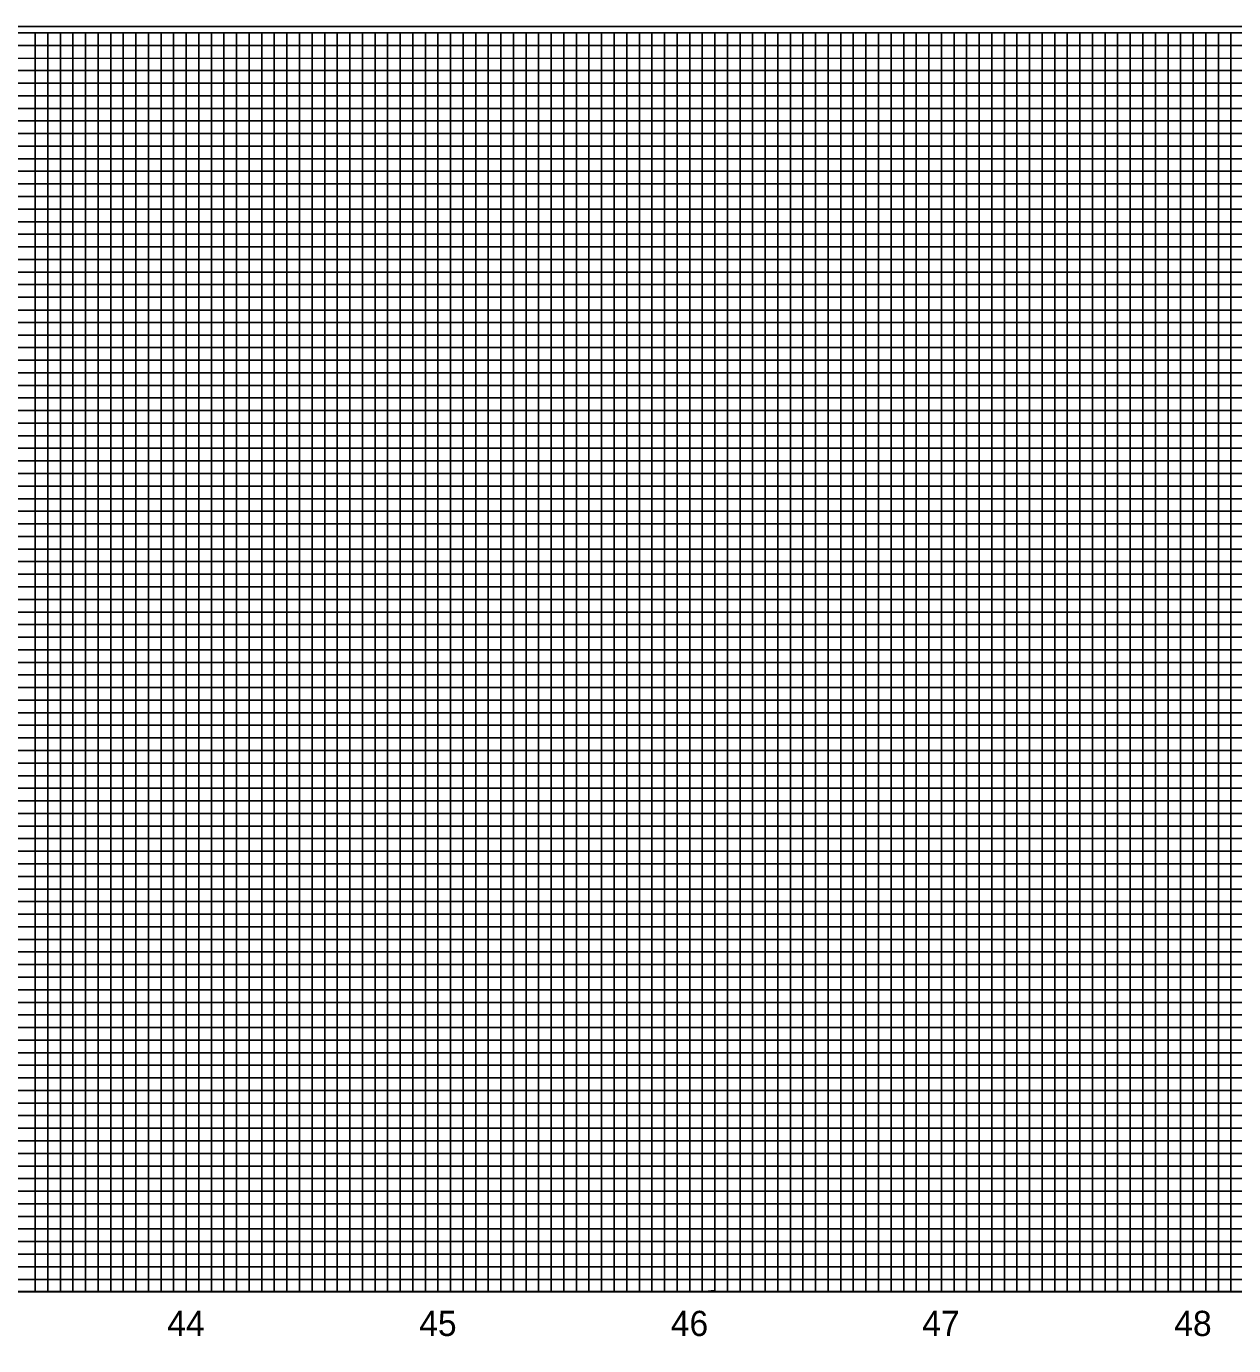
# Model space of a CAD drawing. Extents: x 1755181 to 1757273, y 729911 to 735411.
# Drawn here: x 1755934 to 1756414, y 733764 to 734288 of the extents above; entities that cross this region are included whole.
import ezdxf

# ---------------------------------------------------------------- set-up
doc = ezdxf.new("R2010")
doc.units = 0
for name, color, linetype in [('Exist Vertical Profile Horizontal Axis Label Major', 7, 'Continuous'), ('Scratch_Level_3', 7, 'Continuous'), ('Sheet DOT Grid CELL', 7, 'Continuous'), ('Sheet Plot Border Inside CELL', 7, 'Continuous'), ('Sheet Profile CELL', 7, 'Continuous'), ('Sheet Profile Grid Major CELL', 7, 'Continuous'), ('Sheet Profile Grid Middle CELL', 7, 'Continuous'), ('Sheet Profile Grid Minor CELL', 7, 'Continuous')]:
    doc.layers.add(name, color=color, linetype=linetype)

msp = doc.modelspace()

# ---------------------------------------------------------------- linework, layer by layer
at = {"layer": 'Scratch_Level_3'}
msp.add_lwpolyline([(1755397.67, 733785.92), (1755397.67, 734285.78), (1756647.65, 734285.78), (1756647.63, 734052.8), (1756797.72, 734052.78), (1756797.72, 733785.92)], close=True, dxfattribs=at)
at = {"layer": 'Sheet DOT Grid CELL'}
for p, q in [((1755947.67, 733785.78), (1755947.67, 734285.78)), ((1755997.67, 733785.78), (1755997.67, 734285.78)), ((1756047.67, 733785.78), (1756047.67, 734285.78)), ((1756097.67, 733785.78), (1756097.67, 734285.78)), ((1756147.67, 733785.78), (1756147.67, 734285.78)), ((1756197.67, 733785.78), (1756197.67, 734285.78)), ((1756247.67, 733785.78), (1756247.67, 734285.78)), ((1756297.67, 733785.78), (1756297.67, 734285.78)), ((1756347.67, 733785.78), (1756347.67, 734285.78)), ((1756397.67, 733785.78), (1756397.67, 734285.78)), ((1756647.62, 734235.78), (1755347.67, 734235.78)), ((1756647.62, 734185.78), (1755347.67, 734185.78)), ((1756647.67, 734135.78), (1755347.67, 734135.78)), ((1756647.63, 734085.78), (1755347.67, 734085.78)), ((1756847.67, 734035.78), (1755347.67, 734035.78)), ((1756847.67, 733985.78), (1755347.67, 733985.78)), ((1756847.67, 733935.78), (1755347.67, 733935.78)), ((1756847.67, 733885.78), (1755347.67, 733885.78)), ((1756847.67, 733835.78), (1755347.67, 733835.78))]:
    msp.add_line(p, q, dxfattribs=at)
at = {"layer": 'Sheet Plot Border Inside CELL'}
msp.add_lwpolyline([(1755193.67, 733233.23), (1756860.17, 733233.23), (1756860.17, 734288.33), (1755193.67, 734288.33)], close=True, dxfattribs=at)
at = {"layer": 'Sheet Profile CELL'}
msp.add_line((1755347.67, 733785.78), (1756847.67, 733785.78), dxfattribs=at)
msp.add_lwpolyline([(1756847.67, 734285.78), (1755347.67, 734285.78), (1755347.67, 733235.78), (1756847.67, 733235.78)], close=True, dxfattribs=at)
at = {"layer": 'Sheet Profile Grid Major CELL'}
for points in [[(1755897.67, 733785.78), (1755947.67, 733785.78), (1755947.67, 734285.78), (1755997.67, 734285.78), (1755997.67, 733785.78), (1756047.67, 733785.78), (1756047.67, 734285.78), (1756097.67, 734285.78), (1756097.67, 733785.78), (1756147.67, 733785.78), (1756147.67, 734285.78), (1756197.67, 734285.78), (1756197.67, 733785.78), (1756247.67, 733785.78), (1756247.67, 734285.78), (1756297.67, 734285.78), (1756297.67, 733785.78), (1756347.67, 733785.78), (1756347.67, 734285.78), (1756397.67, 734285.78), (1756397.67, 733785.78), (1756447.67, 733785.78)], [(1755347.67, 734235.78), (1756647.67, 734235.78)], [(1756647.67, 734185.78), (1755347.67, 734185.78), (1755347.67, 734135.78), (1756647.67, 734135.78)], [(1756647.63, 734085.78), (1755347.67, 734085.78), (1755347.67, 734035.78), (1756847.67, 734035.78)], [(1756847.67, 733985.78), (1755347.67, 733985.78), (1755347.67, 733935.78), (1756847.67, 733935.78)], [(1756847.67, 733885.78), (1755347.67, 733885.78), (1755347.67, 733885.78), (1755347.67, 733835.78), (1756847.67, 733835.78)]]:
    msp.add_lwpolyline(points, dxfattribs=at)
at = {"layer": 'Sheet Profile Grid Middle CELL'}
msp.add_line((1755347.67, 734260.78), (1756647.62, 734260.78), dxfattribs=at)
for points in [[(1755922.67, 733785.78), (1755972.67, 733785.78), (1755972.67, 733785.78), (1755972.67, 734285.78), (1756022.67, 734285.78), (1756022.67, 733785.78), (1756072.67, 733785.78), (1756072.67, 734285.78), (1756122.67, 734285.78), (1756122.67, 733785.78), (1756172.67, 733785.78), (1756172.67, 734285.78), (1756222.67, 734285.78), (1756222.67, 733785.78), (1756272.67, 733785.78), (1756272.67, 734285.78), (1756322.67, 734285.78), (1756322.67, 733785.78), (1756372.67, 733785.78), (1756372.67, 734285.78), (1756422.67, 734285.78)], [(1756647.67, 734210.78), (1755347.67, 734210.78), (1755347.67, 734160.78), (1756647.67, 734160.78)], [(1756647.62, 734110.78), (1755347.67, 734110.78), (1755347.67, 734060.78), (1756647.63, 734060.78)], [(1756847.67, 734010.78), (1755347.67, 734010.78), (1755347.67, 733960.78), (1756847.67, 733960.78)], [(1756847.67, 733910.78), (1755347.67, 733910.78), (1755347.67, 733860.78), (1756847.67, 733860.78)], [(1756847.67, 733810.78), (1755347.67, 733810.78)]]:
    msp.add_lwpolyline(points, dxfattribs=at)
at = {"layer": 'Sheet Profile Grid Minor CELL'}
for p, q in [((1755397.67, 734280.78), (1756647.67, 734280.78)), ((1756647.67, 734275.78), (1755397.67, 734275.43)), ((1755397.67, 734270.78), (1756647.67, 734270.78)), ((1756647.62, 734150.78), (1755397.67, 734150.78)), ((1756647.67, 734145.78), (1755397.67, 734145.78)), ((1756647.67, 734140.78), (1755397.67, 734140.78)), ((1755397.67, 734130.78), (1756647.67, 734130.78)), ((1756647.67, 734125.78), (1755397.67, 734125.78)), ((1755397.67, 734120.78), (1756647.62, 734120.78)), ((1756647.62, 734100.78), (1755397.67, 734100.78)), ((1755397.67, 734095.78), (1756647.62, 734095.78)), ((1756647.63, 734075.78), (1755397.67, 734075.78)), ((1755397.67, 734070.78), (1756647.63, 734070.78)), ((1756797.67, 734050.78), (1755397.67, 734050.78)), ((1755397.67, 734045.78), (1756797.67, 734045.78)), ((1756797.67, 734040.78), (1755397.67, 734040.78)), ((1755397.67, 734030.78), (1756797.67, 734030.78)), ((1756797.67, 734025.78), (1755397.67, 734025.78)), ((1755397.67, 734020.78), (1756797.67, 734020.78)), ((1756797.67, 734015.78), (1755397.67, 734015.78)), ((1755397.67, 734005.78), (1756797.67, 734005.78)), ((1756797.67, 734000.78), (1755397.67, 734000.78)), ((1755397.67, 733995.78), (1756797.67, 733995.78)), ((1756797.67, 733990.78), (1755397.67, 733990.78)), ((1755397.67, 733980.78), (1756797.67, 733980.78)), ((1756797.67, 733975.78), (1755397.67, 733975.78)), ((1755397.67, 733970.78), (1756797.67, 733970.78)), ((1756797.67, 733965.78), (1755397.67, 733965.78)), ((1755397.67, 733955.78), (1756797.67, 733955.78)), ((1756797.67, 733950.78), (1755397.67, 733950.78)), ((1755397.67, 733945.78), (1756797.67, 733945.78)), ((1756797.67, 733940.78), (1755397.67, 733940.78)), ((1755397.67, 733930.78), (1756797.67, 733930.78)), ((1756797.67, 733925.78), (1755397.67, 733925.78)), ((1755397.67, 733920.78), (1756797.67, 733920.78)), ((1756797.67, 733915.78), (1755397.67, 733915.78)), ((1755397.67, 733905.78), (1756797.67, 733905.78)), ((1756797.67, 733900.78), (1755397.67, 733900.78)), ((1756797.67, 733895.78), (1755397.67, 733895.78)), ((1756797.67, 733890.78), (1755397.67, 733890.78)), ((1755397.67, 733880.78), (1756797.67, 733880.78)), ((1756797.67, 733875.78), (1755397.67, 733875.78)), ((1755397.67, 733870.78), (1756797.67, 733870.78)), ((1756797.67, 733865.78), (1755397.67, 733865.78)), ((1755397.67, 733855.78), (1756797.67, 733855.78)), ((1756797.67, 733850.78), (1755397.67, 733850.78)), ((1755397.67, 733845.78), (1756797.67, 733845.78)), ((1756797.67, 733840.78), (1755397.67, 733840.78)), ((1755397.67, 733830.78), (1756797.67, 733830.78)), ((1756797.67, 733825.78), (1755397.67, 733825.78)), ((1755397.67, 733820.78), (1756797.67, 733820.78)), ((1756797.67, 733815.78), (1755397.67, 733815.78)), ((1755397.67, 733805.78), (1756797.67, 733805.78)), ((1756797.67, 733800.78), (1755397.67, 733800.78)), ((1755397.67, 733795.78), (1756797.67, 733795.78))]:
    msp.add_line(p, q, dxfattribs=at)
for points in [[(1755932.67, 734285.78), (1755937.67, 734285.78), (1755937.67, 733785.78), (1755942.67, 733785.78), (1755942.67, 734285.78), (1755952.67, 734285.78), (1755952.67, 733785.78), (1755957.67, 733785.78), (1755957.67, 734285.78), (1755962.67, 734285.78), (1755962.67, 733785.78), (1755967.67, 733785.78), (1755967.67, 734285.78), (1755977.67, 734285.78), (1755977.67, 733785.78), (1755982.67, 733785.78), (1755982.67, 734285.78), (1755987.67, 734285.78), (1755987.67, 733785.78), (1755992.67, 733785.78), (1755992.67, 734285.78), (1756002.67, 734285.78), (1756002.67, 733785.78), (1756007.67, 733785.78), (1756007.67, 734285.78), (1756012.67, 734285.78), (1756012.67, 733785.78), (1756017.67, 733785.78), (1756017.67, 734285.78), (1756027.67, 734285.78), (1756027.67, 733785.78), (1756032.67, 733785.78), (1756032.67, 734285.78), (1756037.67, 734285.78), (1756037.67, 733785.78), (1756042.67, 733785.78), (1756042.67, 734285.78), (1756052.67, 734285.78), (1756052.67, 733785.78), (1756052.67, 733785.78), (1756057.67, 733785.78), (1756057.67, 734285.78), (1756062.67, 734285.78), (1756062.67, 733785.78), (1756067.67, 733785.78), (1756067.67, 734285.78), (1756077.67, 734285.78), (1756077.67, 733785.78), (1756082.67, 733785.78), (1756082.67, 734285.78), (1756087.67, 734285.78), (1756087.67, 733785.78), (1756092.67, 733785.78), (1756092.67, 734285.78), (1756102.67, 734285.78), (1756102.67, 733785.78), (1756107.67, 733785.78), (1756107.67, 734285.78), (1756112.67, 734285.78), (1756112.67, 733785.78), (1756117.67, 733785.78), (1756117.67, 734285.78), (1756127.67, 734285.78), (1756127.67, 733785.78), (1756132.67, 733785.78), (1756132.67, 734285.78), (1756137.67, 734285.78), (1756137.67, 733785.78), (1756142.67, 733785.78), (1756142.67, 734285.78), (1756152.67, 734285.78), (1756152.67, 733785.78), (1756157.67, 733785.78), (1756157.67, 734285.78), (1756162.67, 734285.78), (1756162.67, 733785.78), (1756167.67, 733785.78), (1756167.67, 734285.78), (1756177.67, 734285.78), (1756177.67, 733785.78), (1756182.67, 733785.78), (1756182.67, 734285.78), (1756187.67, 734285.78), (1756187.67, 733785.78), (1756192.67, 733785.78), (1756192.67, 734285.78), (1756202.67, 734285.78), (1756202.67, 733785.78), (1756207.37, 733786.33), (1756207.67, 733785.78), (1756207.67, 734285.78), (1756212.67, 734285.78), (1756212.67, 733785.78), (1756217.67, 733785.78), (1756217.67, 734285.78), (1756227.67, 734285.78), (1756227.67, 733785.78), (1756232.67, 733785.78)], [(1756232.67, 733785.78), (1756232.67, 734285.78), (1756237.67, 734285.78), (1756237.67, 733785.78), (1756242.67, 733785.78), (1756242.67, 734285.78), (1756252.67, 734285.78), (1756252.67, 733785.78), (1756257.67, 733785.78), (1756257.67, 734285.78), (1756262.67, 734285.78), (1756262.67, 733785.78), (1756267.67, 733785.78), (1756267.67, 734285.78), (1756277.67, 734285.78), (1756277.67, 733785.78), (1756282.67, 733785.78), (1756282.67, 734285.78), (1756287.67, 734285.78), (1756287.67, 733785.78), (1756292.67, 733785.78), (1756292.67, 734285.78), (1756302.67, 734285.78), (1756302.67, 733785.78), (1756307.67, 733785.78), (1756307.67, 734285.78), (1756312.67, 734285.78), (1756312.67, 733785.78), (1756317.67, 733785.78), (1756317.67, 734285.78), (1756327.67, 734285.78), (1756327.67, 733785.78), (1756332.67, 733785.78), (1756332.67, 734285.78), (1756337.67, 734285.78), (1756337.67, 733785.78), (1756342.67, 733785.78), (1756342.67, 734285.78), (1756352.67, 734285.78), (1756352.67, 733785.78), (1756357.67, 733785.78), (1756357.67, 734285.78), (1756362.67, 734285.78), (1756362.67, 733785.78), (1756367.67, 733785.78), (1756367.67, 734285.78), (1756377.67, 734285.78), (1756377.67, 733785.78), (1756382.67, 733785.78), (1756382.67, 734285.78), (1756387.67, 734285.78), (1756387.67, 733785.78), (1756392.67, 733785.78), (1756392.67, 734285.78), (1756402.67, 734285.78), (1756402.67, 733785.78), (1756407.67, 733785.78), (1756407.67, 734285.78), (1756412.67, 734285.78), (1756412.67, 733785.78), (1756417.67, 733785.78)], [(1756647.67, 734265.78), (1755397.67, 734265.78), (1755397.67, 734255.78), (1756647.67, 734255.78)], [(1756647.62, 734250.78), (1755397.67, 734250.78), (1755397.67, 734245.78), (1756647.67, 734245.78)], [(1756647.67, 734240.78), (1755397.67, 734240.78), (1755397.67, 734230.78), (1756647.67, 734230.78)], [(1756647.67, 734225.78), (1755397.67, 734225.78), (1755397.67, 734220.78), (1756647.67, 734220.78)], [(1756647.67, 734215.78), (1755397.67, 734215.78), (1755397.67, 734205.78), (1756647.67, 734205.78)], [(1756647.67, 734200.78), (1755397.67, 734200.78), (1755397.67, 734195.78), (1756647.67, 734195.78)], [(1756647.67, 734190.78), (1755397.67, 734190.78), (1755397.67, 734180.78), (1756647.67, 734180.78)], [(1756647.67, 734175.68), (1755397.77, 734175.68), (1755397.77, 734170.78), (1756647.67, 734170.78)], [(1756647.67, 734165.78), (1755397.67, 734165.78), (1755397.67, 734155.78), (1756647.67, 734155.78)], [(1756647.62, 734115.78), (1755397.67, 734115.78), (1755397.67, 734105.78), (1756647.62, 734105.78)], [(1756647.62, 734090.78), (1755397.67, 734090.78), (1755397.67, 734080.78), (1756647.63, 734080.78)], [(1756647.63, 734065.78), (1755397.67, 734065.78), (1755397.67, 734055.78), (1756647.63, 734055.78)], [(1756797.67, 733790.78), (1755397.67, 733790.78)]]:
    msp.add_lwpolyline(points, dxfattribs=at)

# ---------------------------------------------------------------- texts
at = {"layer": 'Exist Vertical Profile Horizontal Axis Label Major'}
for s, p in [('44', (1755990.12, 733768.28)), ('45', (1756090.21, 733768.28)), ('46', (1756190.15, 733768.28)), ('47', (1756290.01, 733768.28)), ('48', (1756390.14, 733768.28))]:
    msp.add_text(s, height=10, dxfattribs=at).set_placement(p)

doc.saveas('drawing.dxf')
